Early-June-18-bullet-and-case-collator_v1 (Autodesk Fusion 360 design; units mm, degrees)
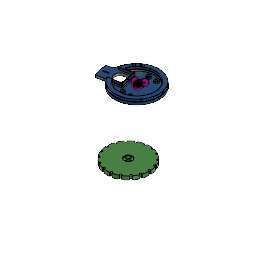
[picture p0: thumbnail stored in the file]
named bodies: "mk1h-bullet-base-feeder-beta", "mk1b-nose-guide", "mk1-flip-ramp", "mk1c-nose-guide-spacer", "mk2b-collator-plate-223", "mk1d-case-feeder-base-6-9", "mk1b-case-feeder-base-centre", "mk1-base-plate-attach", "mk1-case-to-pole", "mk1d-case-feeder-base-3-6", "mk1c-base-to-slinky flange", "mk1g-base-wall-beta", "mk1d-case-feeder-base-9-12", "mk1d-case-feeder-base-12-3", "obsolete-mk1c-case-side-12-3", "mk2b-case-feeder-centre-motor", "mk1b-case-side-6-9", "mk1b-case-side-3-6", "mk1c-case-side-9-12", "mk1-case-collator-base-9-12", "mk1-case-collator-base-6-9", "mk1-case-collator-base-3-6", "mk1-case-collator-base-12-3", "mk1-case-collator-base-centre", "mk1b-case-plate-223-6-9", "mk1b-case-plate-223-9-12", "mk1b-case-plate-223-12-3", "mk1b-case-plate-223-3-6", "mk1b-case-plate-centre", "mk1b-bullet-steady-spring", "mk1b-lh-45deg-leg", "mk1b-rh-45deg-leg", "mk2b-recessed-collator-plate-223", "mk2c8-plus8mm-recessed-collator-plate-223", "mk2d-55gr-70deg-4mm-collator-plate-223", "mk1-b-leg-feet-extended", "mk1-original-flip-ramp (1)", "mk2-flip-ramp", "mk1b-nose-guide-spacer", "mk2g-62gr-70deg-3mm-collator-plate-223-beta", "mk2e-ii-62gr-70deg-4mm-collator-plate-223", "mk1-inside-scraper"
